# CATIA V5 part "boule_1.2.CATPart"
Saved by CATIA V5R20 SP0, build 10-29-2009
Part number: boule_1.2
Bounding box of the stored display mesh (mm): x 430.778 to 526.604, y -701.148 to -601.166, z -702.087 to -602.095
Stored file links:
  D:\thinkmotion-MPB\Dropbox\MMS_GR3\CFAO_2010_bfoltzer\CFAO_bfoltzer\boule_1.2.CATPart
  D:\ecole\thinkmotion\Eolienne.CATProduct
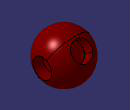
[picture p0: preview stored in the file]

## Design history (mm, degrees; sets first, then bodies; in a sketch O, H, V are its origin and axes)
External parameters (linked from other documents)
  External.rayon_barre = 20 mm
Set1
  Plane1: linked copy from another document
  Point1 to Point3: linked copy from another document
  Line1: linked copy from another document
  Point4: linked copy from another document
  Plane2: linked copy from another document
  Plane3: linked copy from another document
Body1 (main body)
  Sketch1 on Plane1, origin (0, 73.0349, -126.3664), H (1, 0, 0), V (0, 0.8092, 0.5875)
    arc A1 centre (480.7782, -894.8969) radius 50 from (530.7782, -894.8969) to (430.7782, -894.8969) ccw
    point P1 (480.7782, -894.8969)
    point P2 (530.7782, -894.8969)
    point P3 (430.7782, -894.8969)
    reference projected point E1 (430.7782, -894.8969) from Point1
    reference projected point E2 (530.7782, -894.8969) from Point2
    reference projected point E3 (480.7782, -894.8969) from Point3
    coincidence: P3 E1, P2 E2, P1 E3
  Shaft1: profile Sketch1, axis Line1, angle 360
  Sketch2 on {plane type Tangent, Support face of Shaft1 from Sketch1.A1, RefPoint Point4}, origin (480.7782, -1703.4174, 882.5215), H (1, 0, 0), V (0, -0.5875, 0.8092)
    point P1 (0, -1860.0502)
    reference projected point E1 (0, -1860.0502) from Point4
    coincidence: E1 P1
  Hole1: placed by Sketch2, at (480.7782, -610.6949, -622.7175) direction (0, -0.8092, -0.5875), diameter 40 {= External.rayon_barre *2}, up to Plane2
  Sketch3 on {plane type Tangent, Support face of Shaft1 from Sketch1.A1, RefPoint Point2}, origin (530.7782, -957.5368, -541.4086), H (0, 1, 0), V (0, 0, -1)
    point P1 (306.3795, 110.6824)
    reference projected point E1 (306.3795, 110.6824) from Point2
    coincidence: E1 P1
  Hole2: placed by Sketch3, at (530.7782, -651.1573, -652.091) direction (-1, 0, 0), diameter 40 {= External.rayon_barre *2}, up to Plane3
